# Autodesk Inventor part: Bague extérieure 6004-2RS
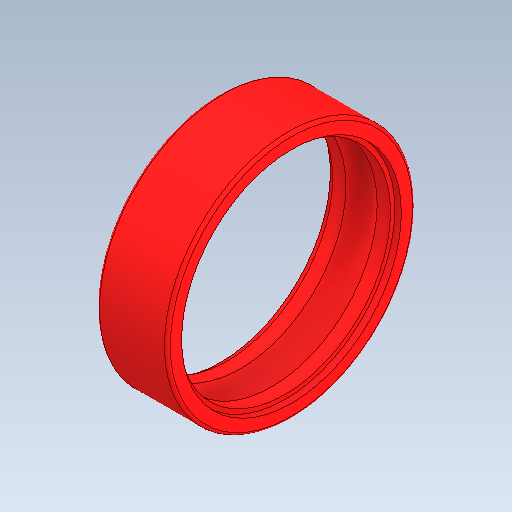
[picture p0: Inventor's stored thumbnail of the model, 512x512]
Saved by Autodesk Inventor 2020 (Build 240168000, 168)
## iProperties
Created: 2003-06
Part Number: Bague extérieure 6004-2RS
Material: Générique
Document SubType Name: Modeling
Designer: Bruno
Density: 1 g/cm^3
Appearance: Par défaut
Author: Bruno
Sending System: SolidWorks 2011
Last Author: Professeur
Last Saved: 2014-11-10
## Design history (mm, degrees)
feature "Base-Révolution"
node "Solide1"
